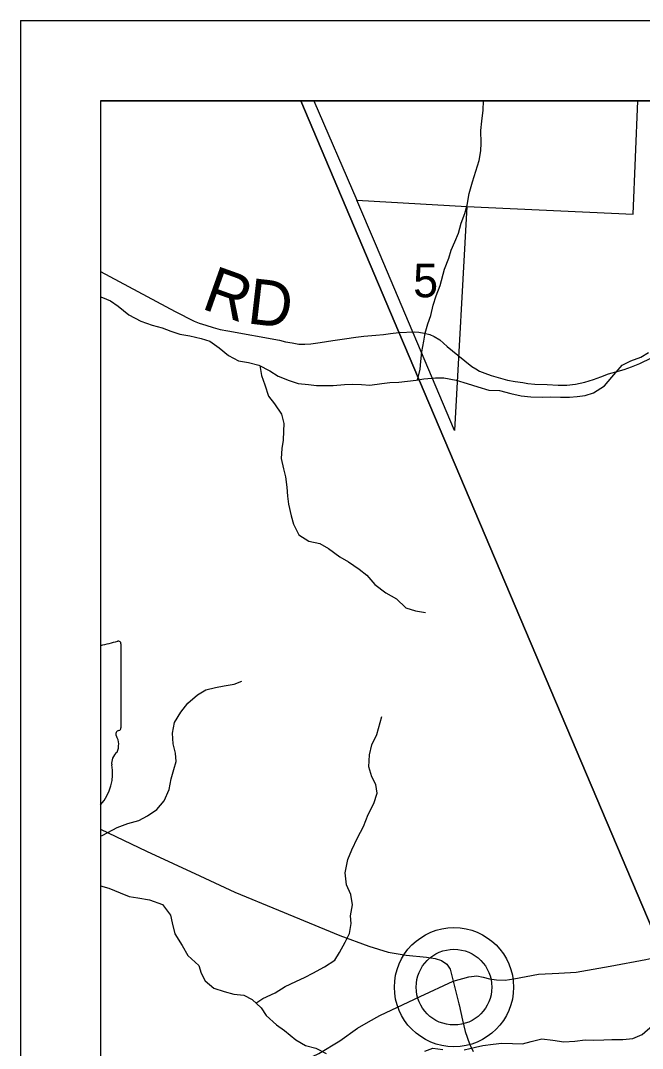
# Model space of a CAD drawing. Extents: x 0 to 44, y -23.8 to 22.
# Drawn here: x 2 to 2.776, y 19.718 to 21 of the extents above; entities that cross this region are included whole.
import ezdxf

# ---------------------------------------------------------------- set-up
doc = ezdxf.new("R2010")
doc.units = 0
for name, color, linetype in [('Default', 7, 'Continuous'), ('GM_X_County_Road', 7, 'Continuous'), ('GM_X_Minor_River', 7, 'Continuous'), ('GM_X_Section', 7, 'Continuous'), ('GM_X_Section_Text', 7, 'Continuous'), ('GM_X_State_Route', 7, 'Continuous'), ('GM_X_Township_Road', 7, 'Continuous'), ('GM_X_Township_Road_Text', 7, 'Continuous'), ('GM_X_Unincorporated', 7, 'Continuous'), ('GM_X_Unincorporated_Location', 7, 'Continuous'), ('SH_Cut_Line', 7, 'Continuous'), ('SH_Data', 7, 'Continuous')]:
    doc.layers.add(name, color=color, linetype=linetype)

msp = doc.modelspace()

# ---------------------------------------------------------------- linework, layer by layer
at = {"layer": 'Default'}
for points in [[(2.3497, 20.9), (2.1, 20.9), (2.1, 14.1), (2.838, 14.1), (3.0317, 14.1856), (3.8639, 14.5533), (4.3443, 14.7655), (4.4538, 14.8144), (4.856, 14.9939), (4.5387, 15.7097), (4.3476, 16.1408), (4.1422, 16.6361), (4.026, 16.9163), (3.7907, 17.4383), (3.763, 17.5087), (3.455, 18.29), (3.1789, 18.9421), (3.1321, 19.0527), (3.0496, 19.2474), (3.0092, 19.3427), (2.8013, 19.8369), (2.472, 20.6113)], [(6.8158, 20.9), (2.3497, 20.9), (2.472, 20.6113), (2.8013, 19.8369), (3.0092, 19.3427), (3.0496, 19.2474), (3.1321, 19.0527), (3.1789, 18.9421), (3.455, 18.29), (3.5135, 19.1552), (3.5139, 19.1608), (3.5639, 19.9016), (3.5995, 20.4294), (3.5996, 20.4304), (3.6002, 20.4391), (3.6191, 20.7184), (3.9141, 20.6975), (4.3639, 20.6657), (6.7023, 20.5094), (6.7107, 20.5383)], [(2.7706, 20.9), (2.3659, 20.9), (2.4199, 20.7761), (2.557, 20.768), (2.7645, 20.7586)]]:
    msp.add_lwpolyline(points, close=True, dxfattribs=at)
at = {"layer": 'GM_X_County_Road'}
for points in [[(2.5401, 19.8019), (2.5594, 19.8074), (2.5697, 19.8084), (2.5774, 19.8068), (2.5854, 19.8048), (2.5942, 19.8037), (2.6048, 19.8032), (2.6157, 19.8049), (2.6466, 19.8107), (2.6718, 19.812), (2.6933, 19.8133), (2.736, 19.8206), (2.7805, 19.8289), (2.7878, 19.8308), (2.7956, 19.8335), (2.8015, 19.8364), (2.8109, 19.8424), (2.8278, 19.8545)], [(2.1, 19.5789), (2.1, 19.5789), (2.1113, 19.585), (2.1195, 19.5885), (2.1291, 19.5921), (2.2169, 19.6262), (2.2346, 19.6325), (2.2504, 19.6405), (2.2632, 19.6475), (2.3037, 19.6763), (2.3134, 19.6821), (2.3486, 19.7004), (2.3724, 19.7119), (2.3984, 19.7276), (2.4207, 19.7435), (2.4344, 19.7514), (2.4486, 19.7592), (2.4987, 19.7829), (2.5401, 19.8019)]]:
    msp.add_lwpolyline(points, dxfattribs=at)
at = {"layer": 'GM_X_Minor_River'}
for points in [[(2.4956, 20.5516), (2.4986, 20.5653), (2.4995, 20.5747), (2.5007, 20.5869), (2.5034, 20.6001), (2.505, 20.61), (2.5085, 20.6217), (2.512, 20.6323), (2.5152, 20.6452), (2.5186, 20.6565), (2.5237, 20.6694), (2.5291, 20.6898), (2.5345, 20.7038), (2.5376, 20.7136), (2.5419, 20.7242), (2.5465, 20.7348), (2.55, 20.7473), (2.5547, 20.7594), (2.5574, 20.7696), (2.5598, 20.7844), (2.5641, 20.7988), (2.5726, 20.8253), (2.5746, 20.8374), (2.575, 20.8469), (2.5744, 20.8628), (2.5756, 20.8745), (2.5773, 20.8882), (2.578, 20.9)], [(2.1, 20.6553), (2.1023, 20.6545), (2.1121, 20.6506), (2.1219, 20.6437), (2.135, 20.633), (2.1501, 20.6249), (2.1641, 20.6199), (2.1769, 20.6167), (2.1875, 20.6125), (2.1988, 20.609), (2.2113, 20.6066), (2.2253, 20.6034), (2.2362, 20.6003), (2.2479, 20.5919), (2.2595, 20.5823), (2.272, 20.5758), (2.2844, 20.5734), (2.2973, 20.5703), (2.3112, 20.5633), (2.3214, 20.5564), (2.3354, 20.551), (2.3467, 20.5475), (2.3592, 20.5459), (2.3694, 20.545), (2.3902, 20.5449), (2.4042, 20.5459), (2.4141, 20.5466), (2.4254, 20.5461), (2.436, 20.5453), (2.4508, 20.5474), (2.461, 20.5485), (2.472, 20.5492), (2.483, 20.5502), (2.4936, 20.5513), (2.5034, 20.5531), (2.5178, 20.5545), (2.5284, 20.5544), (2.5439, 20.5513), (2.5575, 20.5474), (2.5707, 20.5431), (2.5843, 20.5392), (2.598, 20.5387), (2.6119, 20.5348)], [(2.6119, 20.5348), (2.6248, 20.532), (2.6369, 20.5308), (2.6509, 20.5303), (2.6611, 20.5306), (2.674, 20.5301), (2.685, 20.5304), (2.6948, 20.5311), (2.7047, 20.5325), (2.7153, 20.5359), (2.729, 20.5445), (2.7378, 20.5554), (2.7511, 20.5701), (2.7618, 20.5757), (2.7743, 20.5802), (2.7838, 20.5858)], [(2.2985, 20.5697), (2.3006, 20.5573), (2.3047, 20.5456), (2.3095, 20.5315), (2.317, 20.5219), (2.3256, 20.509), (2.3285, 20.4976), (2.3284, 20.4877), (2.3276, 20.4767), (2.326, 20.4661), (2.3251, 20.4536), (2.3281, 20.4411), (2.3306, 20.4308), (2.3324, 20.4179), (2.3331, 20.4069), (2.3345, 20.397), (2.3378, 20.3822), (2.3408, 20.3719), (2.3475, 20.3586), (2.3599, 20.3509), (2.3735, 20.3478), (2.3844, 20.3416), (2.3984, 20.3313), (2.4093, 20.3251), (2.4225, 20.3156), (2.4322, 20.3083), (2.442, 20.2968), (2.4559, 20.2861), (2.4691, 20.2788), (2.4808, 20.2677), (2.4928, 20.2638), (2.5053, 20.2618)], [(2.1, 19.9826), (2.1026, 19.984), (2.1205, 19.9937), (2.1338, 19.9985), (2.1478, 20.0022), (2.1585, 20.0082), (2.1699, 20.016), (2.1794, 20.027), (2.1856, 20.041), (2.188, 20.0542), (2.1915, 20.0659), (2.1942, 20.0758), (2.1935, 20.0864), (2.1906, 20.0978), (2.1896, 20.1111), (2.1923, 20.1247), (2.2, 20.1375), (2.2088, 20.1485), (2.221, 20.159), (2.2313, 20.1654), (2.2434, 20.1683), (2.254, 20.1701), (2.2665, 20.1723), (2.2764, 20.176)], [(2.2938, 19.7746), (2.3024, 19.7803), (2.3176, 19.7874), (2.3302, 19.7952), (2.3435, 19.8016), (2.3552, 19.8068), (2.3647, 19.812), (2.3792, 19.8199), (2.3921, 19.8281), (2.3979, 19.8379), (2.4052, 19.8504), (2.4105, 19.8613), (2.4125, 19.8738), (2.4119, 19.8833), (2.4142, 19.897), (2.4121, 19.9099), (2.4069, 19.922), (2.4051, 19.9372), (2.4086, 19.9535), (2.4136, 19.9656), (2.4206, 19.9807), (2.4279, 19.9947), (2.4337, 20.0098), (2.441, 20.0234), (2.4449, 20.0363), (2.4434, 20.0473), (2.4386, 20.0568), (2.4345, 20.0693), (2.4354, 20.0841), (2.4385, 20.0966), (2.4447, 20.1095), (2.4509, 20.1322)], [(2.1, 19.921), (2.1104, 19.9179), (2.1244, 19.9121), (2.1357, 19.9075), (2.1463, 19.9059), (2.1611, 19.9035), (2.1773, 19.8977), (2.187, 19.8843), (2.1892, 19.8745), (2.1925, 19.8608), (2.2019, 19.8463), (2.209, 19.8341), (2.2225, 19.8215), (2.2254, 19.812), (2.2303, 19.8025), (2.2412, 19.7933), (2.254, 19.789), (2.2661, 19.7859), (2.2786, 19.7843), (2.2891, 19.7789), (2.3004, 19.7685), (2.3064, 19.759), (2.3196, 19.7475), (2.3293, 19.7403), (2.3436, 19.7288), (2.3557, 19.7218), (2.3685, 19.7183), (2.3814, 19.7118)], [(2.5536, 19.7161), (2.5677, 19.7198), (2.5771, 19.7216), (2.59, 19.7234), (2.6006, 19.7245), (2.6142, 19.724), (2.6264, 19.7239), (2.6374, 19.7268), (2.6506, 19.7301), (2.6642, 19.7285), (2.6782, 19.7261), (2.6919, 19.7272), (2.7047, 19.7286), (2.7153, 19.7285), (2.7282, 19.7288), (2.7381, 19.7291), (2.7517, 19.7294), (2.7642, 19.7304), (2.776, 19.7356), (2.7889, 19.7465)], [(2.5048, 19.7146), (2.5146, 19.7183), (2.5271, 19.7167)]]:
    msp.add_lwpolyline(points, dxfattribs=at)
at = {"layer": 'GM_X_Section'}
msp.add_lwpolyline([(2.4199, 20.7761), (2.557, 20.768), (2.5416, 20.4888), (2.443, 20.7216)], close=True, dxfattribs=at)
at = {"layer": 'GM_X_State_Route'}
for points in [[(2.1, 19.9914), (2.1573, 19.9642), (2.2237, 19.9332), (2.2673, 19.9131), (2.3218, 19.8907), (2.3986, 19.8591), (2.4346, 19.8454), (2.4587, 19.838), (2.4814, 19.8345), (2.5068, 19.8318), (2.5174, 19.8303), (2.5253, 19.8278), (2.532, 19.8231), (2.5361, 19.8168), (2.5401, 19.8019), (2.5471, 19.7735)], [(2.5471, 19.7735), (2.5473, 19.7726), (2.5517, 19.7534), (2.5551, 19.7391), (2.5602, 19.7236), (2.5648, 19.7141)]]:
    msp.add_lwpolyline(points, dxfattribs=at)
at = {"layer": 'GM_X_Township_Road'}
for points in [[(2.1, 20.6871), (2.1928, 20.6373), (2.2166, 20.6252), (2.2229, 20.6227), (2.2311, 20.6199), (2.2405, 20.6172), (2.2493, 20.6149), (2.2587, 20.613), (2.323, 20.6013), (2.3308, 20.5992), (2.3389, 20.5982), (2.3473, 20.5963), (2.355, 20.5965), (2.3624, 20.5969), (2.3739, 20.5986), (2.3899, 20.6011)], [(2.3899, 20.6011), (2.3927, 20.6015), (2.4042, 20.603), (2.4185, 20.6053), (2.4283, 20.6063), (2.4434, 20.6076), (2.453, 20.6084), (2.4616, 20.6095), (2.4722, 20.6108), (2.4918, 20.6118), (2.497, 20.6114)], [(2.497, 20.6114), (2.5039, 20.6103), (2.511, 20.6084), (2.5163, 20.6061), (2.5232, 20.6019), (2.5324, 20.5936), (2.5459, 20.5826)], [(2.5459, 20.5826), (2.5632, 20.5686), (2.5682, 20.5655), (2.573, 20.5628), (2.5793, 20.5601), (2.5875, 20.5573), (2.596, 20.5548), (2.6078, 20.5517), (2.6174, 20.5498), (2.6268, 20.5485), (2.6333, 20.5473), (2.6421, 20.5467), (2.6572, 20.546), (2.671, 20.5454), (2.6817, 20.5452), (2.6928, 20.5465), (2.7043, 20.5492), (2.7152, 20.5525), (2.7244, 20.5557), (2.734, 20.5592), (2.7428, 20.5617), (2.7533, 20.5647), (2.7625, 20.5682), (2.7728, 20.5722), (2.7874, 20.5795)]]:
    msp.add_lwpolyline(points, dxfattribs=at)
at = {"layer": 'GM_X_Unincorporated'}
msp.add_line((2.1, 20.2208), (2.1, 20.0217), dxfattribs=at)
msp.add_lwpolyline([(2.1253, 20.118), (2.1253, 20.118), (2.1254, 20.1179), (2.1254, 20.2228)], dxfattribs=at)
for radius in [0.0744, 0.0472]:
    msp.add_circle((2.541, 19.7945), radius, dxfattribs=at)
for centre, major_axis, start_param, end_param in [((2.008, 20.4905), (0.3495, 0), 4.978859, 5.042369), ((2.1217, 20.2231), (0.00367, 0), 6.197627, 7.989034), ((2.1245, 20.1103), (0.00568, 0), 1.883978, 3.671073), ((2.1214, 20.1175), (0.00393, 0), 5.05454, 6.418171), ((2.0884, 20.097), (0.0341, 0), 5.934695, 6.695948), ((2.1385, 20.0741), (0.0248, 0), 2.387724, 3.262537), ((2.0275, 20.0608), (0.0874, 0), 5.689401, 6.440018)]:
    msp.add_ellipse(centre, major_axis=major_axis, ratio=0.8, start_param=start_param, end_param=end_param, dxfattribs=at)
at = {"layer": 'GM_X_Unincorporated_Location'}
msp.add_line((2.541, 19.7945), (2.541, 19.7945), dxfattribs=at)
at = {"layer": 'SH_Cut_Line'}
msp.add_lwpolyline([(4.3476, 16.1408), (4.1422, 16.6361), (4.026, 16.9163), (3.7907, 17.4383), (3.763, 17.5087), (3.455, 18.29), (3.5135, 19.1552), (3.5139, 19.1608), (3.5639, 19.9016), (3.5995, 20.4294), (3.5996, 20.4304), (3.6002, 20.4391), (3.6191, 20.7184), (3.9141, 20.6975), (4.3639, 20.6657), (6.7023, 20.5094), (6.7107, 20.5383), (6.8158, 20.9), (2.1, 20.9), (2.1, 14.1)], dxfattribs=at)
at = {"layer": 'SH_Data'}
for p, q in [((2, 21), (9, 21)), ((2, 21), (2, 14)), ((2.1, 20.9), (2.1, 14.1)), ((2.1, 20.9), (8.9, 20.9))]:
    msp.add_line(p, q, dxfattribs=at)

# ---------------------------------------------------------------- texts
at = {"layer": 'GM_X_Section_Text'}
msp.add_text('5', height=0.0419, rotation=0, dxfattribs=at).set_placement((2.49, 20.6549))
at = {"layer": 'GM_X_Township_Road_Text'}
for s, rotation, p in [('R', 340.3992, (2.2243, 20.6413)), ('D', 353.358, (2.2817, 20.6225))]:
    msp.add_text(s, height=0.0568, rotation=rotation, dxfattribs=at).set_placement(p)

doc.saveas('drawing.dxf')
